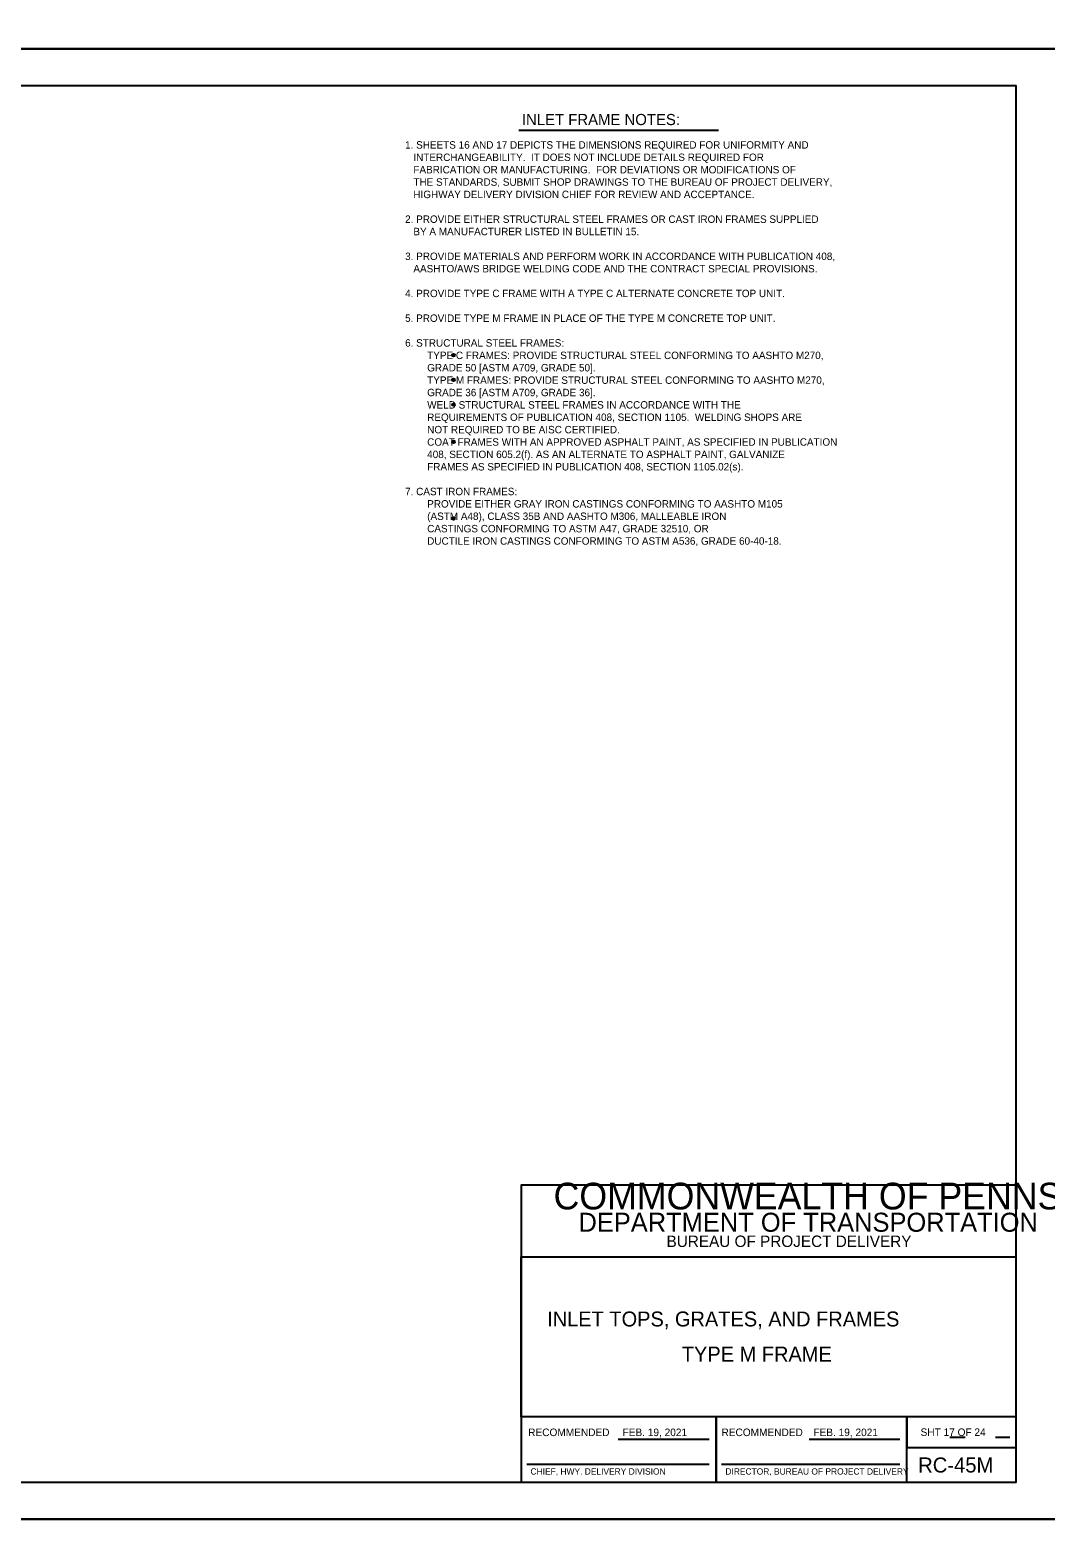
# Model space of a CAD drawing. Extents: x 2087776 to 2104538, y 970919 to 982612.
# Drawn here: x 2097453 to 2098799, y 974792 to 976790 of the extents above; entities that cross this region are included whole.
import ezdxf

# ---------------------------------------------------------------- set-up
doc = ezdxf.new("R2010")
doc.units = 0
doc.layers.add('1', color=7, linetype='Continuous')
doc.layers.add('PLT-BNDY', color=7, linetype='Continuous')

msp = doc.modelspace()

# ---------------------------------------------------------------- linework, layer by layer
at = {"layer": '1'}
for p, q in [((2098101, 976657.8), (2098365.4, 976657.8)), ((2098232.7, 974923.2), (2098353.1, 974923.2)), ((2098485.4, 974923.2), (2098605.8, 974923.2)), ((2098672.1, 974925.9), (2098692.2, 974925.9)), ((2098732.6, 974925.9), (2098751.4, 974925.9)), ((2098111.6, 974890.2), (2098353.1, 974890.2)), ((2098369.3, 974890.2), (2098605.8, 974890.2))]:
    msp.add_line(p, q, dxfattribs=at)
msp.add_lwpolyline([(2098759.9, 974866.2), (2098759.9, 976716.6), (2096181.2, 976716.6), (2096181.2, 974866.2), (2098759.9, 974866.2), (2098759.9, 974952.7), (2098103.8, 974952.7), (2098103.8, 975164.9), (2098759.9, 975164.9), (2098759.9, 975259.9), (2098103.8, 975259.9), (2098103.8, 974866.2), (2098362.3, 974866.2), (2098362.3, 974952.7), (2098362.3, 974866.2), (2098614.9, 974866.2), (2098614.9, 974952.7), (2098614.9, 974912.3), (2098759.9, 974912.3)], dxfattribs=at)
for centre, radius in [((2098014.2, 976359.7), 1.75), ((2098014.2, 976359.7), 1.31), ((2098014.2, 976359.7), 0.875), ((2098014.2, 976359.7), 0.437), ((2098014.2, 976326.9), 1.75), ((2098014.2, 976326.9), 1.31), ((2098014.2, 976326.9), 0.875), ((2098014.2, 976326.9), 0.437), ((2098014.2, 976294.1), 1.75), ((2098014.2, 976294.1), 1.31), ((2098014.2, 976294.1), 0.875), ((2098014.2, 976294.1), 0.437), ((2098014.2, 976244.9), 1.75), ((2098014.2, 976244.9), 1.31), ((2098014.2, 976244.9), 0.875), ((2098014.2, 976244.9), 0.437), ((2098014.2, 976143.4), 1.75), ((2098014.2, 976143.4), 1.31), ((2098014.2, 976143.4), 0.875), ((2098014.2, 976143.4), 0.437)]:
    msp.add_circle(centre, radius, dxfattribs=at)
at = {"layer": 'PLT-BNDY'}
for points in [[(2096053.2, 978714.6), (2098812.4, 978714.6), (2098812.4, 976765.8), (2096053.2, 976765.8)], [(2096053.2, 976765.8), (2098812.4, 976765.8), (2098812.4, 974817), (2096053.2, 974817)], [(2096053.2, 974817), (2098812.4, 974817), (2098812.4, 972868.2), (2096053.2, 972868.2)]]:
    msp.add_lwpolyline(points, close=True, dxfattribs=at)

# ---------------------------------------------------------------- texts
at = {"layer": '1'}
for s, height, p in [('INLET FRAME NOTES:', 14.764, (2098104.9, 976664.6)), ('1. SHEETS 16 AND 17 DEPICTS THE DIMENSIONS REQUIRED FOR UNIFORMITY AND', 9.843, (2097950.2, 976633.4)), ('   INTERCHANGEABILITY.  IT DOES NOT INCLUDE DETAILS REQUIRED FOR', 9.843, (2097950.2, 976617)), ('   FABRICATION OR MANUFACTURING.  FOR DEVIATIONS OR MODIFICATIONS OF', 9.843, (2097950.2, 976600.6)), ('   THE STANDARDS, SUBMIT SHOP DRAWINGS TO THE BUREAU OF PROJECT DELIVERY,', 9.843, (2097950.2, 976584.2)), ('   HIGHWAY DELIVERY DIVISION CHIEF FOR REVIEW AND ACCEPTANCE.', 9.843, (2097950.2, 976567.8)), ('2. PROVIDE EITHER STRUCTURAL STEEL FRAMES OR CAST IRON FRAMES SUPPLIED', 9.843, (2097950.2, 976535)), ('   BY A MANUFACTURER LISTED IN BULLETIN 15.', 9.843, (2097950.2, 976518.6)), ('3. PROVIDE MATERIALS AND PERFORM WORK IN ACCORDANCE WITH PUBLICATION 408,', 9.843, (2097950.2, 976485.8)), ('   AASHTO/AWS BRIDGE WELDING CODE AND THE CONTRACT SPECIAL PROVISIONS.', 9.843, (2097950.2, 976469.4)), ('4. PROVIDE TYPE C FRAME WITH A TYPE C ALTERNATE CONCRETE TOP UNIT.', 9.843, (2097950.2, 976436.6)), ('5. PROVIDE TYPE M FRAME IN PLACE OF THE TYPE M CONCRETE TOP UNIT.', 9.843, (2097950.2, 976403.8)), ('6. STRUCTURAL STEEL FRAMES:', 9.843, (2097950.2, 976371)), ('        TYPE C FRAMES: PROVIDE STRUCTURAL STEEL CONFORMING TO AASHTO M270,', 9.843, (2097950.2, 976354.5)), ('        GRADE 50 [ASTM A709, GRADE 50].', 9.843, (2097950.2, 976338.1)), ('        TYPE M FRAMES: PROVIDE STRUCTURAL STEEL CONFORMING TO AASHTO M270, ', 9.843, (2097950.2, 976321.7)), ('        WELD STRUCTURAL STEEL FRAMES IN ACCORDANCE WITH THE', 9.843, (2097950.2, 976288.9)), ('        GRADE 36 [ASTM A709, GRADE 36].', 9.843, (2097950.2, 976305.3)), ('        REQUIREMENTS OF PUBLICATION 408, SECTION 1105.  WELDING SHOPS ARE', 9.843, (2097950.2, 976272.5)), ('        NOT REQUIRED TO BE AISC CERTIFIED.', 9.843, (2097950.2, 976256.1)), ('        COAT FRAMES WITH AN APPROVED ASPHALT PAINT, AS SPECIFIED IN PUBLICATION', 9.843, (2097950.2, 976239.7)), ('        408, SECTION 605.2(f). AS AN ALTERNATE TO ASPHALT PAINT, GALVANIZE', 9.843, (2097950.2, 976223.3)), ('        FRAMES AS SPECIFIED IN PUBLICATION 408, SECTION 1105.02(s).', 9.843, (2097950.2, 976206.9)), ('7. CAST IRON FRAMES:', 9.843, (2097950.2, 976174.1)), ('        PROVIDE EITHER GRAY IRON CASTINGS CONFORMING TO AASHTO M105', 9.843, (2097950.2, 976157.7)), ('        (ASTM A48), CLASS 35B AND AASHTO M306, MALLEABLE IRON', 9.843, (2097950.2, 976141.3)), ('        CASTINGS CONFORMING TO ASTM A47, GRADE 32510, OR', 9.843, (2097950.2, 976124.9)), ('        DUCTILE IRON CASTINGS CONFORMING TO ASTM A536, GRADE 60-40-18.', 9.843, (2097950.2, 976108.5)), ('COMMONWEALTH OF PENNSYLVANIA', 35.379, (2098146.9, 975227.6)), ('DEPARTMENT OF TRANSPORTATION', 25.211, (2098179.9, 975198)), ('BUREAU OF PROJECT DELIVERY', 15.164, (2098296.6, 975177.8)), ('INLET TOPS, GRATES, AND FRAMES', 19.816, (2098138.4, 975072.5)), ('TYPE M FRAME', 19.816, (2098316.8, 975026)), ('RECOMMENDED', 10, (2098113.3, 974927.2)), ('FEB. 19, 2021', 10, (2098238.3, 974927.2)), ('RECOMMENDED', 10, (2098369.4, 974927.2)), ('FEB. 19, 2021', 10, (2098491.2, 974927.2)), ('SHT 17 OF 24', 10, (2098633.2, 974927.4)), ('CHIEF, HWY. DELIVERY DIVISION', 8.333, (2098116.4, 974876.2)), ('DIRECTOR, BUREAU OF PROJECT DELIVERY', 8.333, (2098374.6, 974876.2)), ('RC-45M', 20, (2098630, 974878.9))]:
    msp.add_text(s, height=height, dxfattribs=at).set_placement(p)

doc.saveas('drawing.dxf')
